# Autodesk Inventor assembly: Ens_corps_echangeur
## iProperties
Shininess: 64.0
Length Units: 11269
Angle Units: 11279
Time Units: 11290
Mass Units: 11283
Length Display Precision: 3
Angle Display Precision: 2
Compacted: True
Created: 2008-02
Part Number: Ens_corps_echangeur
Document SubType Name: Assembly
Designer: Pascal
Density: 0.0
Volumn: 0.0
Area: 0.0
PropertySet Name: Model Information
Control State: 0
Master: False
Checked Out: False
Author: Pascal
